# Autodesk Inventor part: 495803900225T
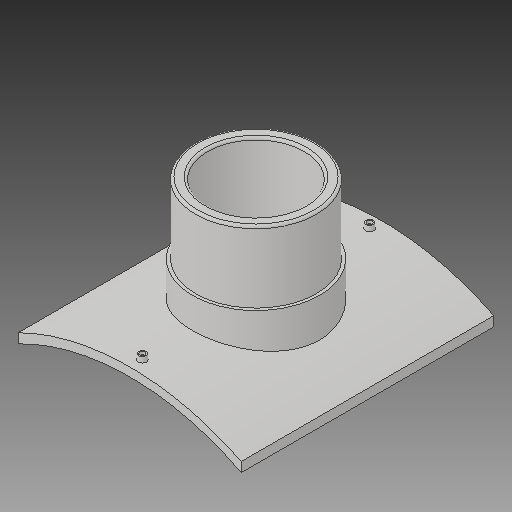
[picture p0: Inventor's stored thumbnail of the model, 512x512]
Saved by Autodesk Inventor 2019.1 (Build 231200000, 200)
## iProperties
Created: 2017-10
Part Number: 495803900225T
Material: Generic
Description: PLASSON BRANCH SADDLE  900x225
Document SubType Name: Modeling
Designer: KIM
Mass: 2754.05 g
Surface Area: 3037.44 cm^2
Volume: 2754.05 cm^3
Density: 1 g/cm^3
Appearance: Default
Author: KIM
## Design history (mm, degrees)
derived "495803.ipt"
feature "Solid1::495803.ipt"
tag "TaggingFeature1"
body "Solid1"
other parameters: "d1" = 16, "d2" = 415, "d4" = 0, "d12" = 475.6, "d13" = 14, "d14" = 211.5, "d16" = 5 deg, "d18" = 4, "d19" = 14, "d20" = 0, "d21" = 3, "d22" = 0, "d23" = 655, "d24" = 236.25, "d25" = 16, "d28" = 0, "d29" = 9.6, "d31" = 0, "d32" = 94.5, "d33" = 0, "d34" = 9, "d36" = 225, "d37" = 132.3, "d38" = 0, "d39" = 4.5, "d_1" = 225, "B_" = 415, "H_" = 189, "x_" = 16, "D_" = 16
